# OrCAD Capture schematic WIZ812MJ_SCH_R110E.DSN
size A3; title: WIZ812MJ; rev: 1.1; company: JaeHo Lee
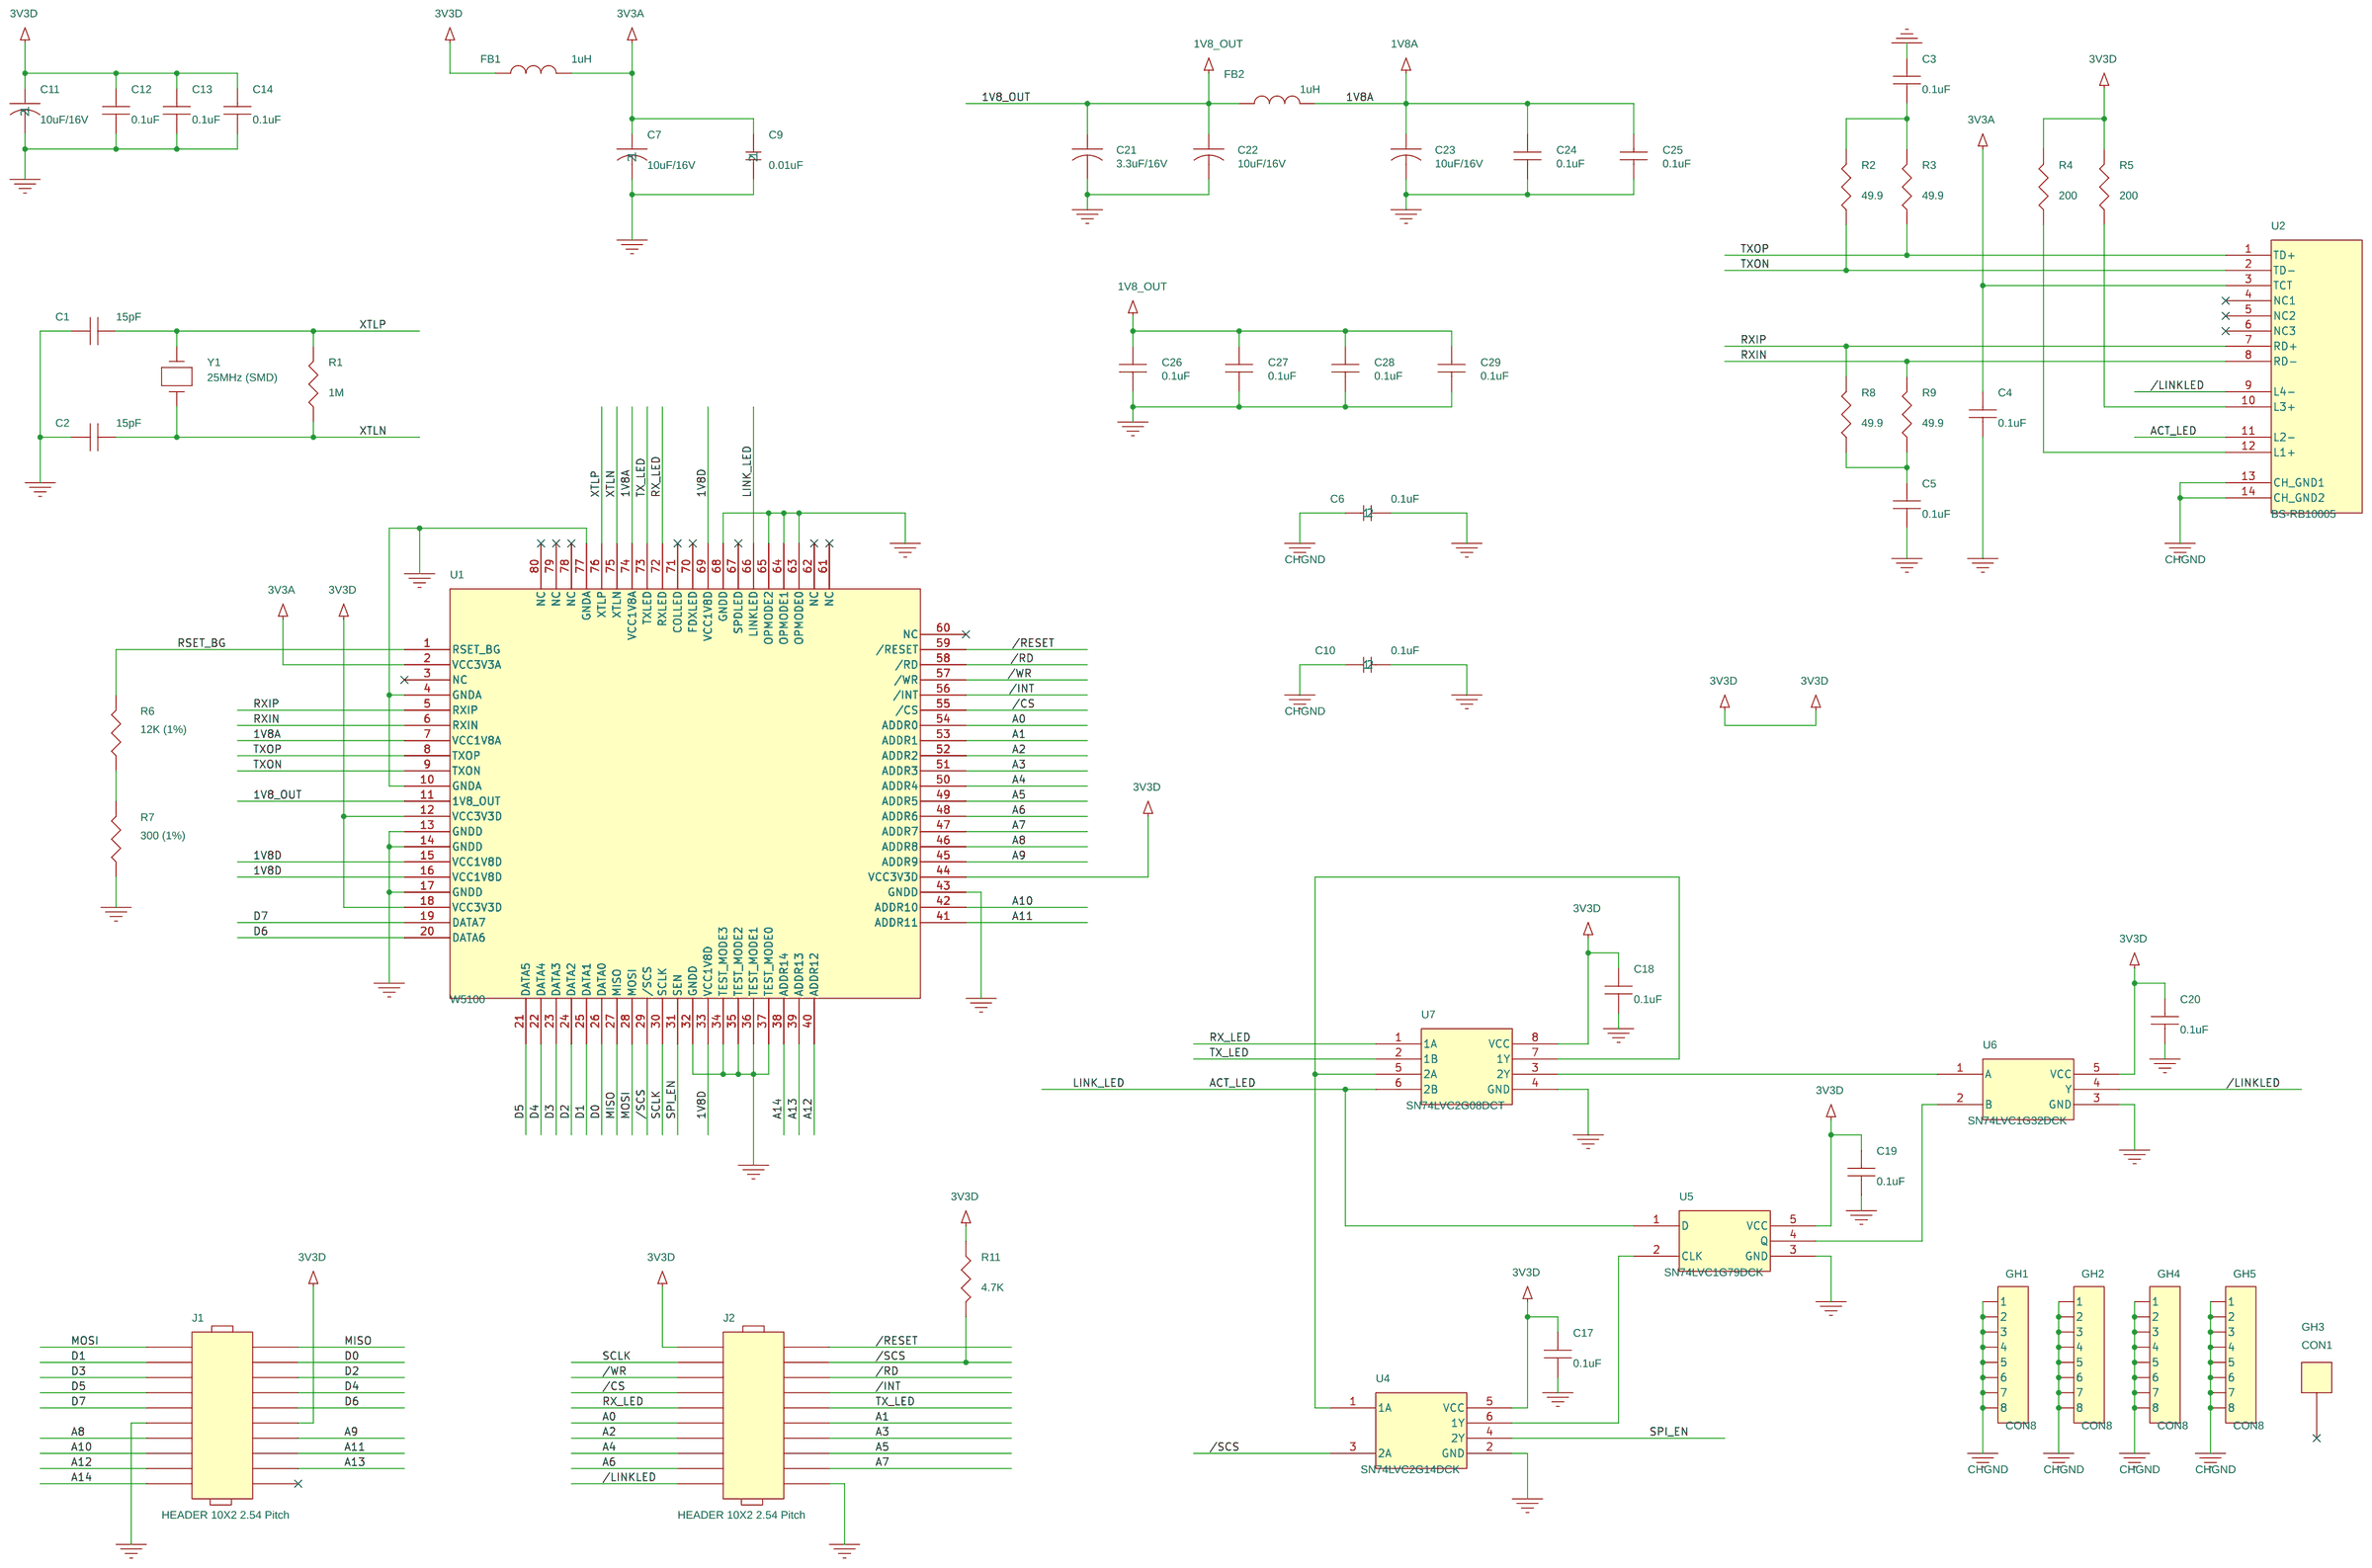
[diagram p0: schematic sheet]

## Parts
C1  15pF
C2  15pF
C3  0.1uF
C4  0.1uF
C5  0.1uF
C6  0.1uF  [C0603]
C7  10uF/16V  [CAP\B\3528]
C9  0.01uF  [C0603]
C10  0.1uF  [C0603]
C11  10uF/16V  [CAP\B\3528]
C12  0.1uF
C13  0.1uF
C14  0.1uF
C17  0.1uF
C18  0.1uF
C19  0.1uF
C20  0.1uF
C21  3.3uF/16V
C22  10uF/16V
C23  10uF/16V
C24  0.1uF
C25  0.1uF
C26  0.1uF
C27  0.1uF
C28  0.1uF
C29  0.1uF
FB1  1uH  [L0805]
FB2  1uH  [L0805]
GH1  CON8
GH2  CON8
GH3  CON1
GH4  CON8
GH5  CON8
J1  HEADER 10X2 2.54 Pitch
J2  HEADER 10X2 2.54 Pitch
R1  1M
R2  49.9
R3  49.9
R4  200
R5  200
R6  12K (1%)
R7  300 (1%)
R8  49.9
R9  49.9
R11  4.7K
U1  W5100
U2  BS-RB10005
U4  SN74LVC2G14DCK
U5  SN74LVC1G79DCK
U6  SN74LVC1G32DCK
U7  SN74LVC2G08DCT
Y1  25MHz (SMD)

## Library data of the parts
C1-C5 C12-C14 C17-C20 C24-C29 = CAP_NP
C6 = CAP_0.01uF_0603_2
C7 = CAP_4.7uF_B_1
C9 = CAP_0.01uF_0603_1
C10 = CAP_0.01uF_0603
C11 = CAP_4.7uF_B
C21-C23 = C
FB1 FB2 = FB_0805
GH1 = CON8_1
GH2 = CON8_3
GH3 = CON1
GH4 = CON8_2
GH5 = CON8
J1 J2 = HEADER_10X2
R1-R9 R11 = R
U1 = W5100_7
U2 = RJ113BZ_0
U4 = SN74AHC1G04_3
U5 = SN74AHC1G04_0
U6 = SN74AHC1G04_1
U7 = SN74AHC1G04_2
Y1 = CRYSTAL

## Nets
1V8A: C23.1 C24.1 C25.1 FB2.2 U1.7(VCC1V8A) U1.74(VCC1V8A)
1V8D: C21.1 C22.1 C26.1 C27.1 C28.1 C29.1 FB2.1 U1.11(1V8_OUT) U1.15(VCC1V8D) U1.16(VCC1V8D) U1.33(VCC1V8D) U1.69(VCC1V8D)
3V3A: C4.1 C7.1 C9.1 FB1.2 U1.2(VCC3V3A) U2.3(TCT)
3V3D: C11.1 C12.1 C13.1 C14.1 C17.1 C18.1 C19.1 C20.1 FB1.1 J1.12 J2.1 R4.2 R5.2 R11.1 U1.12(VCC3V3D) U1.18(VCC3V3D) U1.44(VCC3V3D) U4.5(VCC) U5.5(VCC) U6.5(VCC) U7.8(VCC)
GND: C1.2 C2.2 C3.1 C4.2 C5.2 C6.2 C7.2 C9.2 C10.2 C11.2 C12.2 C13.2 C14.2 C17.2 C18.2 C19.2 C20.2 C21.2 C22.2 C23.2 C24.2 C25.2 C26.2 C27.2 C28.2 C29.2 J1.11 J2.20 R7.1 U1.4(GNDA) U1.10(GNDA) U1.13(GNDD) U1.14(GNDD) U1.17(GNDD) U1.32(GNDD) U1.34(TEST_MODE3) U1.35(TEST_MODE2) U1.36(TEST_MODE1) U1.37(TEST_MODE0) U1.43(GNDD) U1.63(OPMODE0) U1.64(OPMODE1) U1.65(OPMODE2) U1.68(GNDD) U1.77(GNDA) U4.2(GND) U5.3(GND) U6.3(GND) U7.4(GND)
/CS: J2.7 U1.55(/CS)
/INT: J2.8 U1.56(/INT)
/LINKLED: J2.19 U2.9(L4-) U6.4(Y)
/RD: J2.6 U1.58(/RD)
/RESET: J2.2 U1.59(/RESET)
/SCS: J2.4 R11.2 U1.29(/SCS) U4.3(2A)
/WR: J2.5 U1.57(/WR)
A0: J2.11 U1.54(ADDR0)
A1: J2.12 U1.53(ADDR1)
A2: J2.13 U1.52(ADDR2)
A3: J2.14 U1.51(ADDR3)
A4: J2.15 U1.50(ADDR4)
A5: J2.16 U1.49(ADDR5)
A6: J2.17 U1.48(ADDR6)
A7: J2.18 U1.47(ADDR7)
A8: J1.13 U1.46(ADDR8)
A9: J1.14 U1.45(ADDR9)
A10: J1.15 U1.42(ADDR10)
A11: J1.16 U1.41(ADDR11)
A12: J1.17 U1.40(ADDR12)
A13: J1.18 U1.39(ADDR13)
A14: J1.19 U1.38(ADDR14)
ACT_LED: U1.66(LINKLED) U2.11(L2-) U5.1(D) U7.6(2B)
CHGND: C6.1 C10.1 GH1.1 GH1.2 GH1.3 GH1.4 GH1.5 GH1.6 GH1.7 GH1.8 GH2.1 GH2.2 GH2.3 GH2.4 GH2.5 GH2.6 GH2.7 GH2.8 GH4.1 GH4.2 GH4.3 GH4.4 GH4.5 GH4.6 GH4.7 GH4.8 GH5.1 GH5.2 GH5.3 GH5.4 GH5.5 GH5.6 GH5.7 GH5.8 U2.13(CH_GND1) U2.14(CH_GND2)
D0: J1.4 U1.26(DATA0)
D1: J1.3 U1.25(DATA1)
D2: J1.6 U1.24(DATA2)
D3: J1.5 U1.23(DATA3)
D4: J1.8 U1.22(DATA4)
D5: J1.7 U1.21(DATA5)
D6: J1.10 U1.20(DATA6)
D7: J1.9 U1.19(DATA7)
MISO: J1.2 U1.27(MISO)
MOSI: J1.1 U1.28(MOSI)
RSET_BG: R6.2 U1.1(RSET_BG)
RX_LED: J2.9 U1.72(RXLED) U7.1(1A)
RXIN: R9.2 U1.6(RXIN) U2.8(RD-)
RXIP: R8.2 U1.5(RXIP) U2.7(RD+)
SCLK: J2.3 U1.30(SCLK)
SPI_EN: U1.31(SEN) U4.4(2Y)
TX_LED: J2.10 U1.73(TXLED) U7.2(1B)
TXON: R2.1 U1.9(TXON) U2.2(TD-)
TXOP: R3.1 U1.8(TXOP) U2.1(TD+)
XTLN: C2.1 R1.1 U1.75(XTLN) Y1.2
XTLP: C1.1 R1.2 U1.76(XTLP) Y1.1
N16777669: R6.1 R7.2
N16777748: R5.1 U2.10(L3+)
N16777792: R4.1 U2.12(L1+)
N16778099: C3.2 R2.2 R3.2
N16778202: C5.1 R8.1 R9.1
N16918747: U4.1(1A) U7.5(2A) U7.7(1Y)
N16921111: U6.1(A) U7.3(2Y)
N16935785: U4.6(1Y) U5.2(CLK)
N16960496: U5.4(Q) U6.2(B)

Not connected (* = marked no-connect by the designer): GH3 1*; J1 20*; U1 3(NC)* 60(NC)* 61(NC)* 62(NC)* 67(SPDLED)* 70(FDXLED)* 71(COLLED)* 78(NC)* 79(NC)* 80(NC)*; U2 4(NC1)* 5(NC2)* 6(NC3)*
